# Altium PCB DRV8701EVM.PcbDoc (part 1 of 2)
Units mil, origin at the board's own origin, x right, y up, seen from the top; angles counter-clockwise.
Board outline 3500 x 2200 mil, 2 copper layers (Top Layer, Bottom Layer), stack 64.8 mil thick; 118 components, 65 nets, 313 pads, 397 vias.
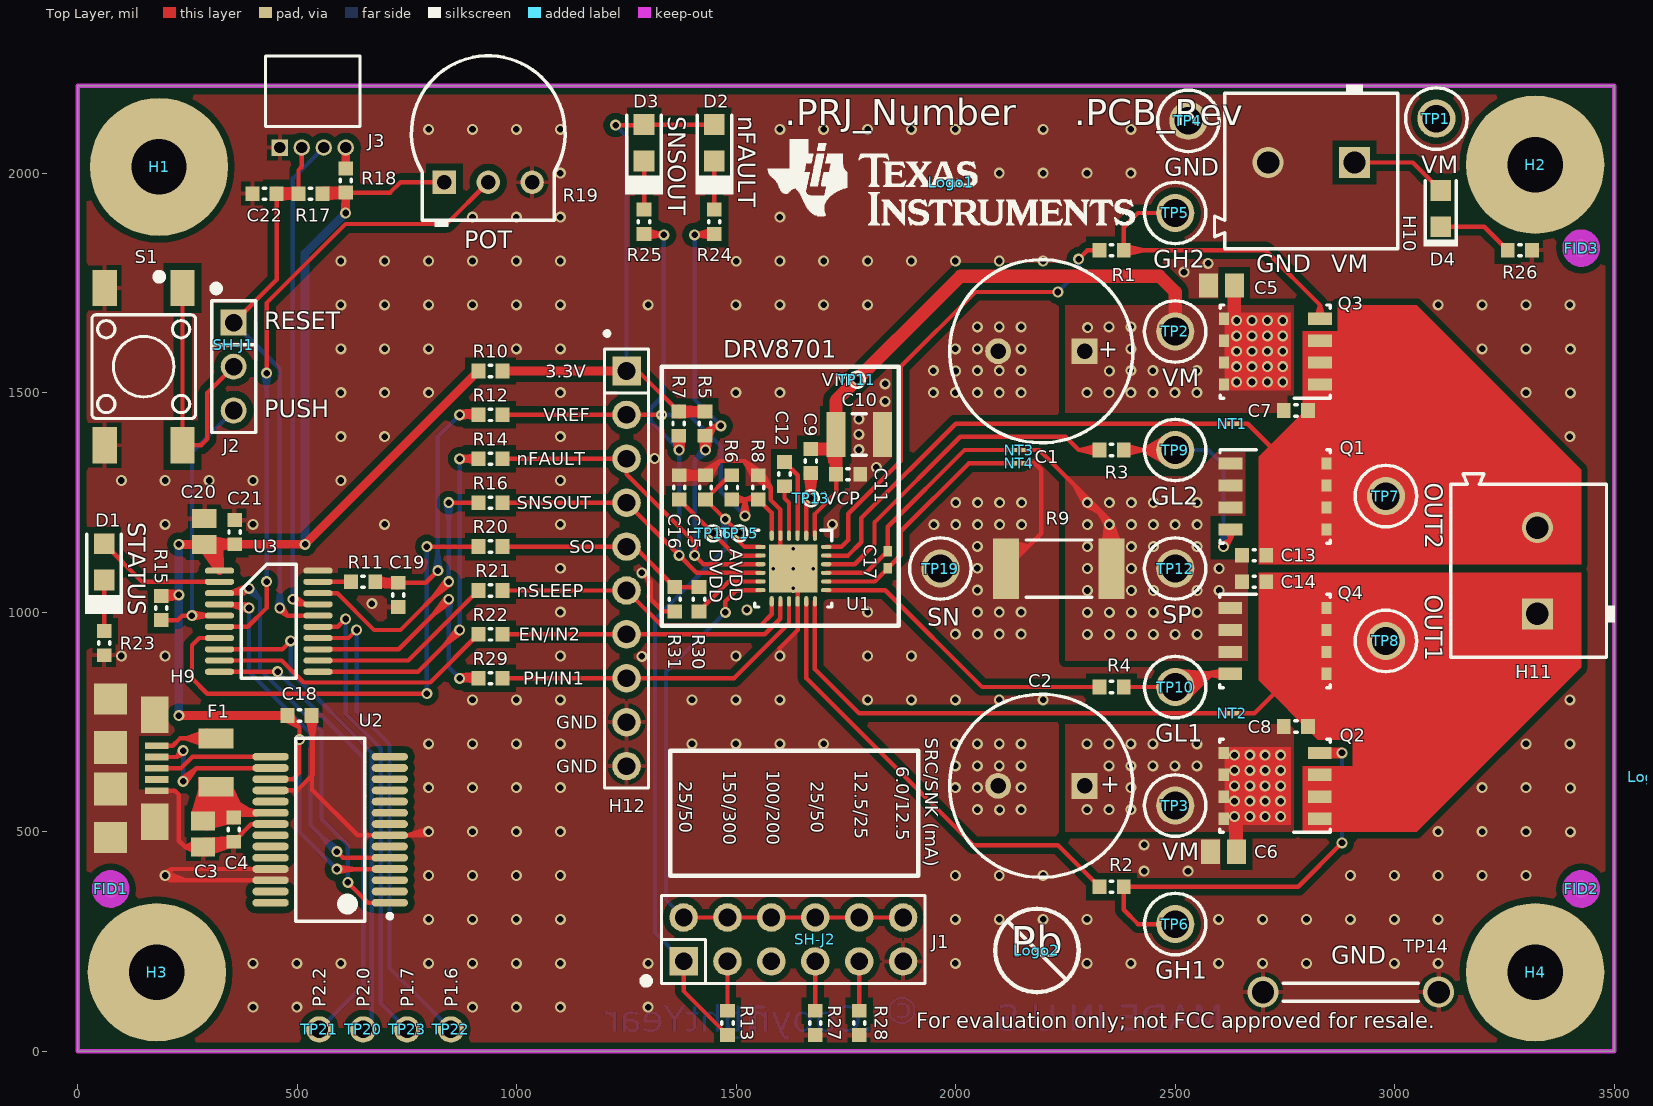
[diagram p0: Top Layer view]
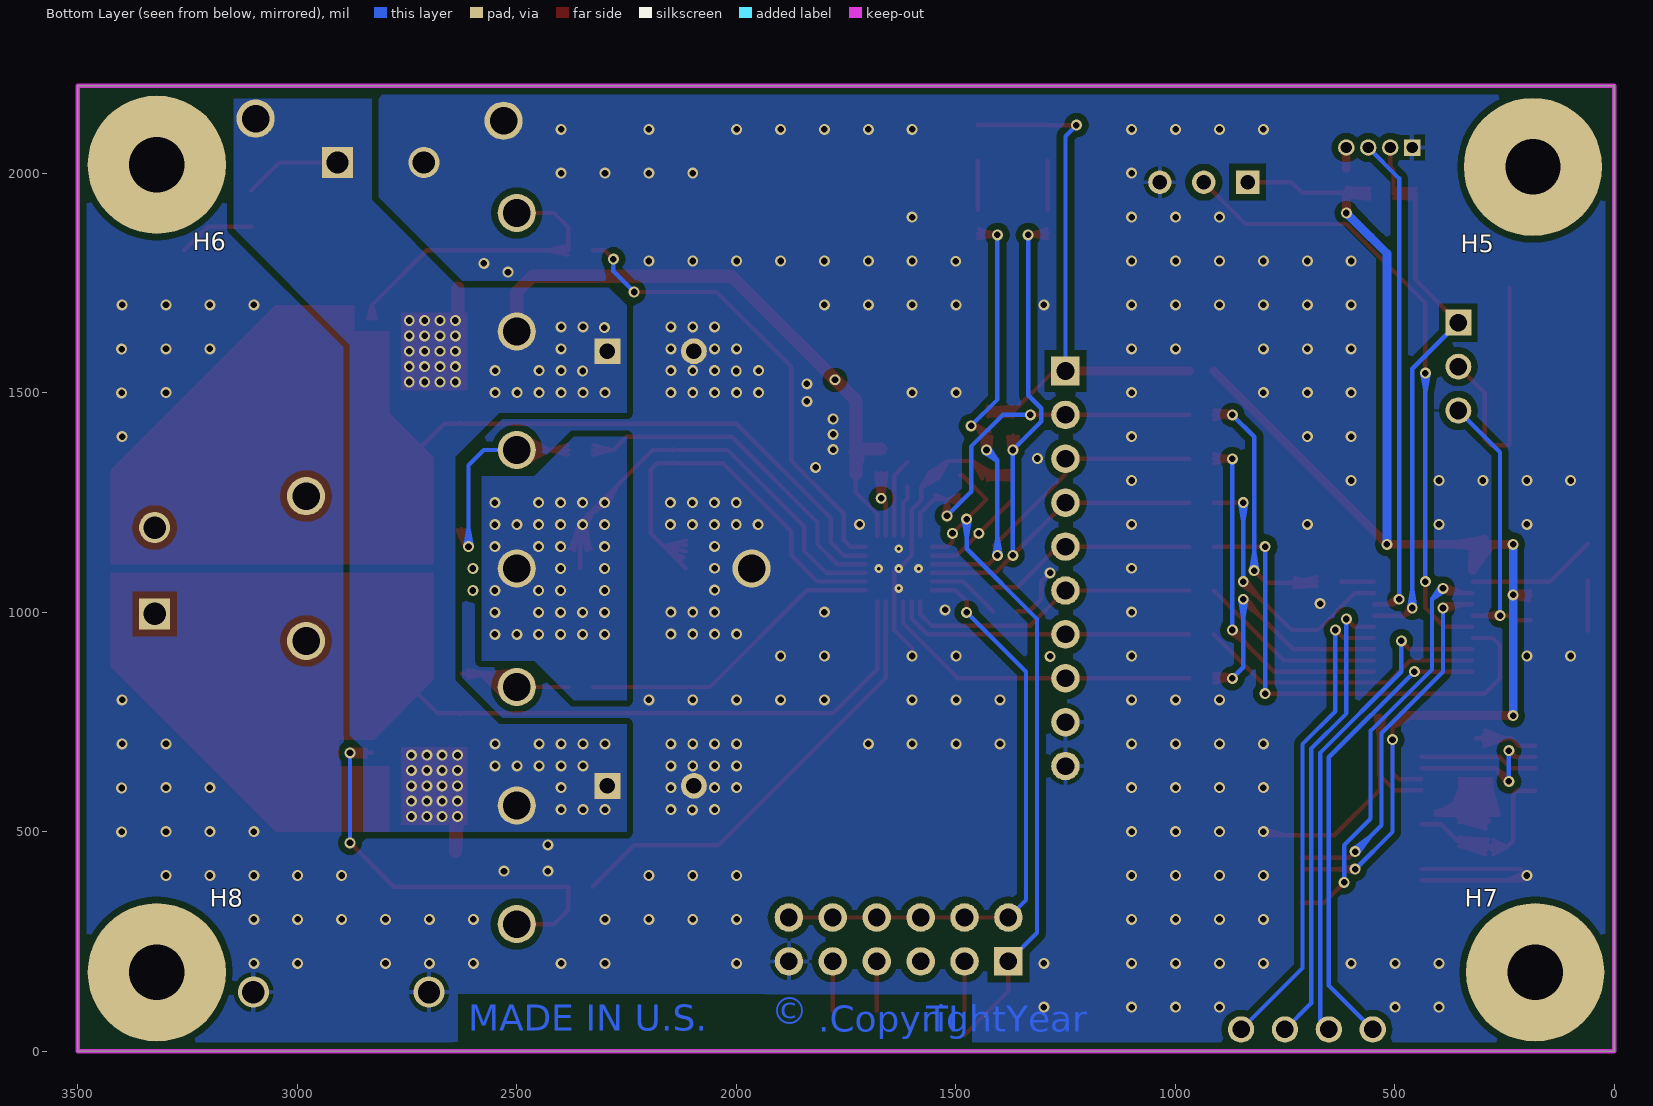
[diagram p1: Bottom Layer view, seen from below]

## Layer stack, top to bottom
Top Layer: signal copper 2.8
Dielectric: core 59.2, FR-4, Dk 4.8
Bottom Layer: signal copper 2.8

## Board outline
0,0 3500,0 3500,2200 0,2200

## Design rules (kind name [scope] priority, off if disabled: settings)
AcuteAngle [All] p1: minimum=4.50000000000000E+0001 checktracksonly=FALSE
AssemblyTestPointUsage [All] p1: valid=2
Clearance Clearance_BoardEdge_MountingHoles [OnCopper and InComponentClass('Mounting Holes') vs IsKeepOut] p1: gap=15
Clearance Clearance_BoardEdge_Poly [OnCopper and InPoly vs IsKeepOut] p2: gap=15
Clearance Clearance_BoardEdge [OnCopper and Not InComponentClass('Logo') and not InComponentClass('FiducialMark') and not InRegion(1000,500,4000,800) and Not IsKeepout vs IsKeepOut] p3: gap=15
Clearance Clearance_Poly [InPolygon] p4: gap=15
Clearance [All] p5: gap=7
ComponentClearance ComponentClearance_Shunt [InComponentClass('Header') vs InComponentClass('Shunt')] p1: gap=0 collisioncheckmode=3 verticalgap=0 showdistances=FALSE
ComponentClearance ComponentClearance_Logo [InComponentClass('Logo')] p2: gap=15 collisioncheckmode=3 verticalgap=10 showdistances=FALSE
ComponentClearance ComponentClearance_ScrewToNut [(HasFootprint('NY PMS 440 0025 PH')) vs (HasFootprint('Keystone_1902C'))] p3: gap=5 collisioncheckmode=3 verticalgap=10 showdistances=FALSE
ComponentClearance ComponentClearance_MountingHoles [InComponentClass('Mounting Holes')] p4: gap=15 collisioncheckmode=3 verticalgap=100000 showdistances=FALSE
ComponentClearance ComponentClearance_SmallPassives [HasFootprint('0201*') or HasFootprint('0402*') or HasFootprint('0508') or HasFootprint('0603*') or HasFootprint('0612') or HasFootprint('0805*') or HasFootprint('0815*') or HasFootprint('0830*') or HasFootprint('1206*') or HasFootprint('1210*') or HasFootprint('1808*') or HasFootprint('1812*') or HasFootprint('1825*') or HasFootprint('2010*') or HasFootprint('2220*') or HasFootprint('2225*') or HasFootprint('2512*') or HasFootprint('2728*') or HasFootprint('3518*') vs HasFootprint('0201*') or HasFootprint('0402*') or HasFootprint('0508') or HasFootprint('0603*') or HasFootprint('0612') or HasFootprint('0805*') or HasFootprint('0815*') or HasFootprint('0830*') or HasFootprint('1206*') or HasFootprint('1210*') or HasFootprint('1808*') or HasFootprint('1812*') or HasFootprint('1825*') or HasFootprint('2010*') or HasFootprint('2220*') or HasFootprint('2225*') or HasFootprint('2512*') or HasFootprint('2728*') or HasFootprint('3518*')] p5: gap=15 collisioncheckmode=3 verticalgap=10 showdistances=FALSE
ComponentClearance ComponentClearance_THtoSMT [IsThruComponent vs IsSMTComponent] p6: gap=15 collisioncheckmode=3 verticalgap=25 showdistances=FALSE
ComponentClearance ComponentClearance_THtoTH [IsThruComponent vs IsThruComponent] p7: gap=15 collisioncheckmode=3 verticalgap=15 showdistances=FALSE
ComponentClearance [All] p8: gap=15 collisioncheckmode=3 verticalgap=10 showdistances=FALSE
DiffPairsRouting [All] p1: maxlimit=100 minlimit=10 mostfreqgap=10 maxuncoupledlength=1000
FabricationTestPointUsage TestPointUsage [All] p1: valid=2 allowmultiple=FALSE
FabricationTestpoint Testpoint [All] p1: side=3 testpointundercomponent=TRUE minsize=40 maxsize=100 preferedsize=60 minholesize=0 maxholesize=40 preferedholesize=32 testpointgrid=1 allowsidetop=TRUE allowsidebottom=TRUE usegrid=TRUE gridtolerance=0.01
FanoutControl Fanout_LCC [IsLCC] p1: bgadir=Out bgaviamode=Centered fanoutstyle=Auto fanoutdirection=Alternating viagrid=1 // Fanout_LCC (Default Rule)
FanoutControl Fanout_BGA [IsBGA] p2: bgadir=Out bgaviamode=Centered fanoutstyle=Auto fanoutdirection=Alternating viagrid=1 // Fanout_BGA (Default Rule)
FanoutControl Fanout_Default [All] p4: bgadir=Out bgaviamode=Centered fanoutstyle=Auto fanoutdirection=Alternating viagrid=1 // Fanout_Default (Default Rule)
FanoutControl Fanout_Small [(CompPinCount < 5)] p5: bgadir=Out bgaviamode=Centered fanoutstyle=Auto fanoutdirection=OutThenIn viagrid=1 // Fanout_Small (Default Rule)
HoleSize [All] p1: absolutevalues=TRUE maxlimit=251 minlimit=8 maxpercent=80.000 minpercent=20.000
MinimumAnnularRing MinimumAnnularRing_ThermalPadVias [IsVia and InAnyComponent] p1: minimumring=3.9
MinimumAnnularRing [All] p2: minimumring=3.9
MinimumSolderMaskSliver MinimumSolderMaskSliver_Logo [InComponentClass('Logo') vs InComponentClass('Logo')] p1: minsoldermaskwidth=0.7
MinimumSolderMaskSliver [All] p2: minsoldermaskwidth=2
PlaneConnect [All] p1: planeconnectstyle=Relief reliefexpansion=10 reliefentries=4 reliefconductorwidth=10 reliefairgap=10
PolygonConnect PolygonConnect_1 [IsNamedPolygon('TOP_GND_PLN') or IsNamedPolygon('BOT_GND_PLN') vs Not (InComponent('U1') or InComponent('U2') or InComponent('U3') or InComponent('Q3') or InComponent('Q4') or InComponent('Q5') or InComponent('Q6') or InComponent('C1') or InComponent('C2') or InComponent('C5') or InComponent('C6') or InComponent('C10') or InComponent('C11') or InComponent('C15') or InComponent('C16') or InComponent('R8') or InComponent('R9') or InComponent('H9') or InComponent('H10') or InComponent('TP4') or IsStitchingVia or IsVia)] p1: connectstyle=Relief reliefconductorwidth=10 reliefentries=4 polygonreliefangle="90 Angle" airgapwidth=10
PolygonConnect [All] p2: connectstyle=Direct reliefconductorwidth=10 reliefentries=4 polygonreliefangle="90 Angle" airgapwidth=10
RoutingVias ThermalPadVias [IsVia and InAnyComponent] p1: holewidth=7.87 width=19.68 viastyle="Through Hole" minholewidth=7.87 minwidth=19.68 maxholewidth=12.99 maxwidth=23.62
RoutingVias [All] p2: holewidth=16 width=34 viastyle="Through Hole" minholewidth=7.87 minwidth=25 maxholewidth=40 maxwidth=65
SMDToCorner [All] p1: distance=30000
SilkToSilkClearance [All] p1: silktosilkclearance=5
SilkscreenOverComponentPads [IsPad] p1: minsilkscreentomaskgap=1.95
SolderMaskExpansion [All] p1: expansion=1.97
Width [All] p1: maxlimit=100 minlimit=6 preferedwidth=10 checkconnectedcopper=TRUE
14 further rules are at their usual default settings.

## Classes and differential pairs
component class Header: H12 J1 J2
component class AssemblyNote: ZZ1 ZZ2 ZZ3 ZZ4
component class DRV8701EVM_HARDWARE: FID1 FID2 FID3 H1 H2 H3 H4 H5 H6 H7 H8 Logo1 Logo2 Logo3 ZZ1 ZZ2 ZZ3 ZZ4
component class Logo: Logo1
component class DRV8701EVM_SCHEMATIC: C1 C2 C3 C4 C5 C6 C7 C8 C9 C10 C11 C12 C13 C14 C15 C16 C17 C18 C19 C20 C21 C22 D1 D2 D3 D4 F1 H9 H10 H11 H12 J1 J2 J3 NT1 NT2 NT3 NT4 Q1 Q2 Q3 Q4 R1 R2 R3 R4 R5 R6 R7 R8 R9 R10 R11 R12 R13 R14 R15 R16 R17 R18 R19 R20 R21 R22 R23 R24 R25 R26 R27 R28 R29 R30 R31 S1 SH-J1 SH-J2 TP1 TP2 TP3 TP4 TP5 TP6 TP7 TP8 TP9 TP10 TP11 TP12 TP13 TP14 TP15 TP16 TP19 TP20 TP21 TP22 TP23 U1 U2 U3
component class Shunt: SH-J1 SH-J2
component class FiducialMark: FID1 FID2 FID3
component class "Mounting Holes": H1 H2 H3 H4

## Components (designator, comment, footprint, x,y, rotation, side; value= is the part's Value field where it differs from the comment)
C1 "ECA-1HM471" M_1000x2000 2195,1595 r180 top
C2 "ECA-1HM471" M_1000x2000 2195,605 r180 top
C3 "C2012X7R1A475M" 0805L 285,495 r270 top
C4 "C0603C104K8RACTU" 0603L 355,505 r270 top
C5 "GRM21BR71H105KA12L" 0805L 2605,1745 r180 top
C6 "GRM21BR71H105KA12L" 0805L 2610,455 r180 top
C7 "DNP" 0603L 2775,1460 r0 top
C8 "DNP" 0603L 2775,740 r0 top
C9 "C1608X7R1C105K" 0603L 1670,1345 r90 top
C10 "GRM32ER71H106KA12L" 1210L 1780,1405 r0 top
C11 "C1608X7R1H104K" 0603L 1755,1315 r0 top
C12 "C1608X7R1H104K" 0603L 1610,1315 r270 top
C13 "DNP" 0603L 2680,1130 r180 top
C14 "DNP" 0603L 2680,1070 r180 top
C15 "GRM188R70J105KA01D" 0603L 1430,1285 r90 top
C16 "GRM188R70J105KA01D" 0603L 1370,1285 r270 top
C17 "GRM155R71C102KA01D" 0402L 1845,1120 r270 top
C18 "C0603C104K8RACTU" 0603L 505,765 r0 top
C19 "GRM188R70J105KA01D" 0603L 730,1040 r270 top
C20 "C2012X7R1A475M" 0805L 288.2,1184.8 r90 top
C21 "C0603C104K8RACTU" 0603L 357.2,1182.8 r90 top
C22 "GRM188R71C102KA01D" 0603L 425.21,1954 r180 top
D1 "LTST-C171GKT" LED_LTST-C171 60,1115 r270 top
D2 "LTST-C170KRKT" LED_LTST-C170 1450,2070 r270 top
D3 "LTST-C170KRKT" LED_LTST-C170 1290,2070 r270 top
D4 "LTST-C171GKT" LED_LTST-C171 3105,1920 r270 top
F1 "1206L050/15YR" 1206_FUSE 315,658 r270 top
FID1 "Fiducial" Fiducial10-20 75,370 r0 top
FID2 "Fiducial" Fiducial10-20 3425,370 r0 top
FID3 "Fiducial" Fiducial10-20 3425,1830 r0 top
H1 "NY PMS 440 0025 PH" "NY PMS 440 0025 PH" 185,2015 r0 top locked
H2 "NY PMS 440 0025 PH" "NY PMS 440 0025 PH" 3320,2020 r0 top locked
H3 "NY PMS 440 0025 PH" "NY PMS 440 0025 PH" 180,180 r0 top locked
H4 "NY PMS 440 0025 PH" "NY PMS 440 0025 PH" 3320,180 r0 top locked
H5 "1902C" Keystone_1902C 185.13,2015.01 r180 bottom
H6 "1902C" Keystone_1902C 3320.36,2020 r180 bottom
H7 "1902C" Keystone_1902C 180.36,180 r180 bottom
H8 "1902C" Keystone_1902C 3320.36,180 r180 bottom
H9 "ZX62-B-5PA(11)" CONN_USB_micro_ZX62-B-5PA 180,645 r270 top
H10 "691 101 710 002" Wurth_691101710002 2810,2025 r180 top
H11 "691 101 710 002" Wurth_691101710002 3325,1095 r90 top
H12 "TSW-110-07-G-S" TSW-110-07-G-S 1250,1100 r270 top
J1 "PEC06DAAN" CONN_PEC06DAAN 1630,255 r0 top
J2 "PEC03SAAN" CONN_PEC03SAAN 355,1560 r270 top
J3 "851-43-004-20-001000" CONN_851-43-004-20-001000 535.21,2059 r180 top
Logo1 "Texas Instruments" TI_Stacked_Overlay_Small 1990,1980 r0 top
Logo2 "Pb-Free Symbol" Pb-Free_Overlay_Medium 2185,230 r0 top
Logo3 "FCC disclaimer" FCC_disclaimer 3583,626 r90 top
NT1 "Net-Tie" Net-Tie_10mil 2630,1430 r0 top
NT2 "Net-Tie" Net-Tie_10mil 2630,770 r0 top
NT3 "Net-Tie" Net-Tie_10mil 2145,1370 r180 top
NT4 "Net-Tie" Net-Tie_10mil 2145,1340 r0 top
Q1 "CSD18532Q5B" TRANS_NexFET_Q5B 2720.3,1594.09 r180 top
Q2 "CSD18532Q5B" TRANS_NexFET_Q5B 2720,605 r180 top
Q3 "CSD18532Q5B" TRANS_NexFET_Q5B 2735.3,1264.09 r0 top
Q4 "CSD18532Q5B" TRANS_NexFET_Q5B 2735,935 r0 top
R1 "CRCW06030000Z0EA" 0603L 2355,1825 r180 top
R2 "CRCW06030000Z0EA" 0603L 2355,375 r0 top
R3 "CRCW06030000Z0EA" 0603L 2355,1370 r180 top
R4 "CRCW06030000Z0EA" 0603L 2355,830 r0 top
R5 "CRCW060310K0JNEA" 0603L 1428.7,1430 r270 top
R6 "DNP" 0603L 1490,1285 r90 top
R7 "CRCW060310K0JNEA" 0603L 1368.7,1430 r270 top
R8 "DNP" 0603L 1550,1285 r270 top
R9 "CRA2512-FZ-R010ELF" 2512M 2235,1100 r0 top
R10 "CRCW06030000Z0EA" 0603L 940,1550 r180 top
R11 "CRCW060310K0JNEA" 0603L 650,1070 r0 top
R12 "CRCW06030000Z0EA" 0603L 940,1450 r180 top
R13 "CRCW060368K0JNEA" 0603L 1480,65 r270 top
R14 "CRCW06030000Z0EA" 0603L 940,1350 r180 top
R15 "CRCW060347K0JNEA" 0603L 190,1010 r90 top
R16 "CRCW06030000Z0EA" 0603L 940,1250 r180 top
R17 "CRCW060347K0JNEA" 0603L 530.21,1954 r0 top
R18 "CRCW06030000Z0EA" 0603L 610.21,1984 r270 top
R19 "3352T-1-503LF" Bourns_3352T 935,1980 r0 top
R20 "CRCW06030000Z0EA" 0603L 940,1150 r180 top
R21 "CRCW06030000Z0EA" 0603L 940,1050 r180 top
R22 "CRCW06030000Z0EA" 0603L 940,950 r180 top
R23 "CRCW0603330RJNEA" 0603L 60,930 r90 top
R24 "CRCW0603330RJNEA" 0603L 1450,1890 r90 top
R25 "CRCW0603330RJNEA" 0603L 1290,1890 r90 top
R26 "CRCW06034K99FKEA" 0603L 3285,1825 r180 top
R27 "CRCW0603200KJNEA" 0603L 1680,65 r90 top
R28 "CRCW060333K0JNEA" 0603L 1780,65 r90 top
R29 "CRCW06030000Z0EA" 0603L 940,850 r180 top
R30 "CRCW06037K50JNEA" 0603L 1415,1030 r270 top
R31 "CRCW060310K0JNEA" 0603L 1360,1030 r270 top
S1 "4-1437565-1" SW_FSM4JSMA 150,1560 r0 top
SH-J1 "969102-0000-DA" SNT-100-BK-G 355,1610 r90 top
SH-J2 "969102-0000-DA" SNT-100-BK-G 1680,255 r90 top
TP1 "5005" Keystone5005 3095,2125 r0 top
TP2 "5005" Keystone5005 2500,1640 r0 top
TP3 "5005" Keystone5005 2500,560 r0 top
TP4 "5006" Keystone5006 2530,2120 r0 top
TP5 "5007" Keystone5007 2500,1910 r0 top
TP6 "5007" Keystone5007 2500,290 r0 top
TP7 "5007" Keystone5007 2980,1265 r0 top
TP8 "5007" Keystone5007 2980,935 r0 top
TP9 "5007" Keystone5007 2500,1370 r0 top
TP10 "5007" Keystone5007 2500,830 r0 top
TP11 "VM" TP_VIA_018RND008 1775,1530 r90 top
TP12 "5006" Keystone5006 2500,1100 r0 top
TP13 "VCP" TP_VIA_018RND008 1670,1260 r180 top
TP14 "D3082-05" Harwin_D3082-05 2900,135 r180 top
TP15 "AVDD" TP_VIA_018RND008 1507.44,1180 r0 top
TP16 "DVDD" TP_VIA_018RND008 1447.44,1180 r90 top
TP19 "5006" Keystone5006 1965,1100 r0 top
TP20 "TESTPOINT" TP_VIA_060RND040 650,50 r90 top
TP21 "TESTPOINT" TP_VIA_060RND040 550,50 r90 top
TP22 "TESTPOINT" TP_VIA_060RND040 850,50 r90 top
TP23 "TESTPOINT" TP_VIA_060RND040 750,50 r90 top
U1 "DRV8701ERGER" RGE0024F 1630,1100 r270 top
U2 "FT232RL" SSOP28_N 575,505 r180 top
U3 "MSP430G2553IPW20" PW0020A_N 435,980 r0 top
ZZ1 "This Assembly Note is for PCB labels only" AssemblyNoteLabel 185,2655 r0 top
ZZ2 "These assemblies are ESD sensitive, ESD precautions shall be observed." AssemblyNote 185,2569.11 r0 top
ZZ3 "These assemblies must be clean and free from flux and all contaminants. Use of no clean flux is not acceptable." AssemblyNote 185,2480.56 r0 top
ZZ4 "These assemblies must comply with workmanship standards IPC-A-610 Class 2, unless otherwise specified." AssemblyNote 185,2395 r0 top

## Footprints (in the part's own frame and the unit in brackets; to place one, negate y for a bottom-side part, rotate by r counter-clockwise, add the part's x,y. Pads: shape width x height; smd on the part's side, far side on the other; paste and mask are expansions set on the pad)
0402L [mm] "0402 from SM-752 data"
  rect 0.6x0.5 smd: 1(-0.5,0) 2(0.5,0)
  body extent -0.55,-0.3 0.55,0.3, height 0.6
0603L [mm] "0603 from SM-752 data"
  rect 0.8x0.85 smd: 1(-0.7,0) 2(0.7,0)
  silkscreen extent -0.07,-0.33 0.07,0.33, body extent -0.87,-0.47 0.87,0.47, height 0.85
0805L [mm] "0805 from SM-752 data"
  rect 1.1x1.4 smd: 1(-0.75,0) 2(0.75,0)
  body extent -1.1,-0.72 1.1,0.72, height 1.1
1206_FUSE [mil]
  rect 45x80 smd mask+2: 1(-55,0) 2(55,0)
1210L [mm] "1210 from SM-752 data"
  rect 1.1x2.6 smd: 1(-1.35,0) 2(1.35,0)
  silkscreen extent -0.4,-1.2 0.4,1.2, body extent -1.7,-1.35 1.7,1.35, height 1.35
2512M [mm] "Chip Resistor, Body 6.3x3.2mm, IPC Low Density"
  rect 1.5x3.5 smd: 1(-3.05,0) 2(3.05,0)
  silkscreen extent -1.9,-1.65 1.9,1.65, body extent -3.22,-1.67 3.22,1.67, height 0.71
AssemblyNote [mil] "Assembly Note"
AssemblyNoteLabel [mil] "Assembly Note for PCB Labels"
Bourns_3352T [mm] "TH, 3-Leads, Body 9.53x8.89mm, Pitch 2.54mm"
  rect 1.35x1.35 hole 0.85: 1(-2.54,0)
  round 1.35 hole 0.85: 2(0,0) 3(2.54,0)
  silkscreen extent -4.44,-2.6 4.44,7.31, body extent -4.44,-2.21 4.45,7.32, height 3.81
CONN_851-43-004-20-001000 [mm] "MILL-MAX"
  rect 0.95x0.95 hole 0.65: 1(1.905,0)
  round 0.95 hole 0.65: 2(0.635,0) 3(-0.635,0) 4(-1.905,0)
  silkscreen extent -2.73,-5.31 2.73,-1.22, body extent -2.73,-5.31 2.73,0.23, height 2.23
CONN_PEC03SAAN [mm] "SULLINS"
  rect 1.5x1.5 hole 1.016: 1(-2.54,0)
  round 1.5 hole 1.016: 2(0,0) 3(2.54,0)
  silkscreen extent -4.72,-1.27 3.81,1.27, body extent -3.84,-1.3 3.84,1.3, height 8.38
CONN_PEC06DAAN [mm] "SULLINS"
  rect 1.65x1.65 hole 1.016 mask+0: 1(-6.35,-1.27)
  round 1.65 hole 1.016 mask+0: 2(-6.35,1.27) 3(-3.81,-1.27) 4(-3.81,1.27) 5(-1.27,-1.27) 6(-1.27,1.27) 7(1.27,-1.27) 8(1.27,1.27) 9(3.81,-1.27) 10(3.81,1.27) 11(6.35,-1.27) 12(6.35,1.27)
  silkscreen extent -8.72,-2.6 7.62,2.54, body extent -7.62,-2.54 7.62,2.54, height 8.38
CONN_USB_micro_ZX62-B-5PA [mm] "Hirose"
  rect 0.4x1.35 smd: 1(-1.3,0) 2(-0.65,0) 3(0,0) 4(0.65,0) 5(1.3,0)
  rect 1.9x1.9 smd: 6(-1.2,-2.675) 7(1.2,-2.675)
  rect 1.8x1.9 smd: 8(-4,-2.675) 9(4,-2.675)
  rect 2.1x1.6 smd: 10(-3.1,-0.125) 11(3.1,-0.125)
  body extent -3.75,-5.32 3.75,0.18, height 2.55
FCC_disclaimer [mil]
Fiducial10-20 [mm]
  round 1 smd paste-0.5 mask+0.5: 1(0,0)
  Top Layer keep-out circle w1.178: c0,0 r0.5
Harwin_D3082-05 [mm] "Shorting Plug, 10.16mm spacing, TH"
  round 1.8 hole 1.3: 1(-5.08,0) 2(5.08,0)
  silkscreen extent -3.9,-0.53 3.9,0.53, body extent -5.6,-0.52 5.61,0.52, height 6.63
Keystone5005 [mil] "Keystone Compact loops"
  round 87 hole 63: 1(0,0)
  silkscreen extent -70,-70 70,70, body extent -63,-63 62,63, height 225
Keystone5006 [mil] "Keystone Compact loops"
  round 87 hole 63: 1(0,0)
  silkscreen extent -70,-70 70,70, body extent -63,-63 62,63, height 225
Keystone5007 [mil] "Keystone Compact loops"
  round 87 hole 63: 1(0,0)
  silkscreen extent -70,-70 70,70, body extent -63,-63 62,63, height 225
Keystone_1902C [mil] "Hex Standoff, 4-40 threaded, nylon"
  round 1 on Mech4: 0(0,0)
  body extent -145,-126 146,126, height 501
LED_LTST-C170 [mm] "LITE-ON"
  rect 1.2x1.2 smd: 1(-1.05,0) 2(1.05,0)
  silkscreen extent -1.6,-1.1 3,1.1, body extent -1.05,-0.67 1.05,0.67, height 1.1
LED_LTST-C171 [mm] "LITE-ON"
  rect 1.2x1.2 smd: 1(-1.05,0) 2(1.05,0)
  silkscreen extent -1.6,-1.1 3,1.1, body extent -1.05,-0.67 1.05,0.67, height 0.8
M_1000x2000 [mm] "Panasonic"
  rect 1.5x1.5 hole 0.9: 1(-2.5,0)
  round 1.5 hole 0.9: 2(2.5,0)
  silkscreen extent -5.3,-5.3 5.3,5.3, body extent -5.21,-5.24 5.24,5.24, height 22.01
Net-Tie_10mil [mil] "10mil net tie, no solder mask opening, no solder paste"
  rect 10x10 smd paste-5 mask-5: 1(-10,0) 2(10,0)
  Top Layer region: -6,5 6,5 6,-5 -6,-5
"NY PMS 440 0025 PH" [mm] "4-40 nylon screw and mounting hole"
  round 8 hole 3.2: 1(0,0)
  body extent -3.3,-3.3 3.3,3.3, height 2.69
Pb-Free_Overlay_Medium [mil]
  silkscreen extent -95,-95 95,95
PW0020A_N [mm] "TSOP, 20-Leads, Body 6.5x4.4mm, Pitch 0.65mm, IPC Medium Density"
  oval 1.7x0.35 smd: 1(-2.85,2.925) 2(-2.85,2.275) 3(-2.85,1.625) 4(-2.85,0.975) 5(-2.85,0.325) 6(-2.85,-0.325) 7(-2.85,-0.975) 8(-2.85,-1.625) 9(-2.85,-2.275) 10(-2.85,-2.925) 11(2.85,-2.925) 12(2.85,-2.275) 13(2.85,-1.625) 14(2.85,-0.975) 15(2.85,-0.325) 16(2.85,0.325) 17(2.85,0.975) 18(2.85,1.625) 19(2.85,2.275) 20(2.85,2.925)
  silkscreen extent -1.6,-3.3 1.6,3.3, body extent -3.21,-3.25 3.21,3.25, height 0.99
RGE0024F [mm] "QFN, 24-Leads, Body 4x4mm, Pitch 0.5mm, Thermal Pad 2.8x2.8mm, TI Recommended"
  oval 0.6x0.24 smd: 1(-1.9,1.25) 2(-1.9,0.75) 3(-1.9,0.25) 4(-1.9,-0.25) 5(-1.9,-0.75) 6(-1.9,-1.25) 13(1.9,-1.25) 14(1.9,-0.75) 15(1.9,-0.25) 16(1.9,0.25) 17(1.9,0.75) 18(1.9,1.25)
  oval 0.24x0.6 smd: 7(-1.25,-1.9) 8(-0.75,-1.9) 9(-0.25,-1.9) 10(0.25,-1.9) 11(0.75,-1.9) 12(1.25,-1.9) 19(1.25,1.9) 20(0.75,1.9) 21(0.25,1.9) 22(-0.25,1.9) 23(-0.75,1.9) 24(-1.25,1.9)
  rect 2.8x2.8 smd paste-1.4: 25(0,0)
  silkscreen extent -2.22,-2.22 2.22,2.22, body extent -2.07,-2.07 2.08,2.08, height 1.01
SNT-100-BK-G [mil] "Samtec STEP model"
  round 1 on Mech3: 0(0,0)
  body extent -100,-50 100,50, height 344
SSOP28_N [mm] "SOP, 28-Leads, Body 10.2x5.3mm, Pitch 0.65mm, IPC Medium Density"
  oval 2.1x0.45 smd mask+0.07: 1(-3.45,4.225) 2(-3.45,3.575) 3(-3.45,2.925) 4(-3.45,2.275) 5(-3.45,1.625) 6(-3.45,0.975) 7(-3.45,0.325) 8(-3.45,-0.325) 9(-3.45,-0.975) 10(-3.45,-1.625) 11(-3.45,-2.275) 12(-3.45,-2.925) 13(-3.45,-3.575) 14(-3.45,-4.225) 15(3.45,-4.225) 16(3.45,-3.575) 17(3.45,-2.925) 18(3.45,-2.275) 19(3.45,-1.625) 20(3.45,-0.975) 21(3.45,-0.325) 22(3.45,0.325) 23(3.45,0.975) 24(3.45,1.625) 25(3.45,2.275) 26(3.45,2.925) 27(3.45,3.575) 28(3.45,4.225)
  silkscreen extent -3.57,-5.3 2,5.3, body extent -2.7,-5.3 2.7,5.3, height 2
SW_FSM4JSMA [mm] "Alcoswitch"
  rect 1.4x2.1 smd: 1(2.25,4.55) 2(2.25,-4.55) 3(-2.25,4.55) 4(-2.25,-4.55)
  silkscreen extent -3,-3 3,5.4, body extent -3,-5 3,5, height 5.1
TI_Stacked_Overlay_Small [mil]
  silkscreen extent -418,-98 418,98
TP_VIA_018RND008 [mil] "TP_VIA_018RND008"
  round 25 hole 15: 1(0,0)
  silkscreen extent -18,-18 18,18
TP_VIA_060RND040 [mil] "TP_VIA_060RND040"
  round 60 hole 40: 1(0,0)
TRANS_NexFET_Q5B [mm] "TI recommended land pattern (nominal) November 2012"
  rect 1.372x0.71 smd paste-0.4: 1(-2.776,1.905) 2(-2.776,0.635) 3(-2.776,-0.635) 4(-2.776,-1.905)
  rect 0.59x0.71 smd paste-0.3: 5(2.776,-1.905) 6(2.776,-0.635) 7(2.776,0.635) 8(2.776,1.905)
  Top Layer region: -1.106,-2.26 2.744,-2.26 2.744,2.26 -1.106,2.26
  silkscreen extent -3.38,-2.7 3,2.7, body extent -3.23,-2.55 2.87,2.55, height 1.06
TSW-110-07-G-S [mm] "Samtec 100mil, 1x10, 230 mil above insulator"
  rect 1.65x1.65 hole 1.016 mask+0: 1(-11.43,0)
  round 1.65 hole 1.016 mask+0: 2(-8.89,0) 3(-6.35,0) 4(-3.81,0) 5(-1.27,0) 6(1.27,0) 7(3.81,0) 8(6.35,0) 9(8.89,0) 10(11.43,0)
  silkscreen extent -13.72,-1.27 12.7,1.27, body extent -12.7,-1.27 12.7,1.27, height 8.38
Wurth_691101710002 [mm] "Terminal Block, 5 mm, 2x1, TH"
  rect 1.8x1.8 hole 1.3: 1(-2.5,0)
  round 1.8 hole 1.3: 2(2.5,0)
  silkscreen extent -5,-4.5 5.6,5, body extent -5.6,-4 5.6,5, height 12.5

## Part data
C1 C2: "CAP, AL, 470 µF, 50 V, +/- 20%,  ohm, TH"
C3 C20: "CAP, CERM, 4.7uF, 10V, +/-20%, X7R, 0805"
C4 C18 C21: "CAP, CERM, 0.1uF, 10V, +/-10%, X7R, 0603"
C5 C6: "CAP, CERM, 1uF, 50V, +/-10%, X7R, 0805"
C7 C8 C13 C14: library part C1608X7R1H103K, "CAP, CERM, 0.01uF, 50V, +/-10%, X7R, 0603"
C9: "CAP, CERM, 1uF, 16V, +/-10%, X7R, 0603"
C10: "CAP, CERM, 10uF, 50V, +/-10%, X7R, 1210"
C11 C12: "CAP, CERM, 0.1uF, 50V, +/-10%, X7R, 0603"
C15 C16 C19: "CAP, CERM, 1uF, 6.3V, +/-10%, X7R, 0603"
C17: "CAP, CERM, 1000pF, 16V, +/-10%, X7R, 0402"
C22: "CAP, CERM, 1000pF, 16V, +/-10%, X7R, 0603"
D1 D4: "LED, Green, SMD"
D2 D3: "LED, Red, SMD"
F1: library part FUSE_1206L_SERIES, "Fuse, Poly Resetable PTC, 0.5A"
FID1 FID2 FID3: "Fiducial mark.  There is nothing to buy or mount."
H1 H2 H3 H4: "Machine Screw, Round, #4-40 x 1/4, Nylon, Philips panhead"
H5 H6 H7 H8: "Standoff, Hex, 0.5\"L #4-40 Nylon"
H9: "Connector, micro USB Type B, Receptacle, R/A, SMD"
H10 H11: "Terminal Block, 5 mm, 2x1, Tin, TH"
H12: "Header, 100mil, 10x1, Gold, TH"
J1: "Header, 100mil, 6x2, Tin, TH"
J2: "Header, 100mil, 3x1, Tin, TH"
J3: "SOCKET .050\" GRID SIP 4 POS R/A, TH"
Logo1: library part TI_Logo, "Texas Instrument Corporate Signature"
Logo2: library part Pb-Free
Logo3: library part FCC_disclaimer, "FCC_disclaimer"
NT1 NT2 NT3 NT4: "Single point connection between nets."
Q1 Q2 Q3 Q4: "MOSFET, N-CH, 60V, 172A, SON 5x6mm"
R1 R2 R3 R4 R10 R12 R14 R16 R18 R20 R21 R22 R29: "RES, 0 ohm, 5%, 0.1W, 0603"
R5 R7 R11: "RES, 10k ohm, 5%, 0.1W, 0603"
R6 R8: library part CRCW06030000Z0EA, "RES, 0 ohm, 5%, 0.1W, 0603"
R9: "RES, 0.01 ohm, 1%, 3W, 2512"
R13: "RES, 68k ohm, 5%, 0.1W, 0603"
R15 R17: "RES, 47k ohm, 5%, 0.1W, 0603"
R19: "Trimming Potentiometer, 50K, 0.5W, TH"
R23 R24 R25: "RES, 330 ohm, 5%, 0.1W, 0603"
R26: "RES, 4.99k ohm, 1%, 0.1W, 0603"
R27: "RES, 200k ohm, 5%, 0.1W, 0603"
R28: "RES, 33k ohm, 5%, 0.1W, 0603"
R30: "RES, 7.5 k, 5%, 0.1 W, 0603"
R31: "RES, 10 k, 5%, 0.1 W, 0603"
S1: "Switch, Tactile, SPST-NO, 0.05A, 12V, SMT"
SH-J1 SH-J2: "Shunt, 100mil, Gold plated, Black"
TP1 TP2 TP3: "Test Point, Compact, Red, TH"
TP4 TP12 TP19: "Test Point, Compact, Black, TH"
TP5 TP6 TP7 TP8 TP9 TP10: "Test Point, Compact, White, TH"
TP11 TP13 TP15 TP16: library part TESTPOINT, "TEST POINT.  No entry in BOM."
TP14: "1mm Uninsulated Shorting Plug, 10.16mm spacing, TH"
TP20 TP21 TP22 TP23: "TEST POINT.  No entry in BOM."
U1: "H-Bridge Gate Driver, RGE0024F"
U2: "USB to Serial UART, SSOP28"
U3: "16 MHz Mixed Signal Microcontroller with 16 KB Flash, 512 B SRAM and 24 GPIOs, -40 to 85 degC, 20-pin SOP (PW), Green (RoHS & no Sb/Br)"
ZZ1: library part AssemblyNoteLabel
ZZ2 ZZ3 ZZ4: library part AssemblyNote

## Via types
v1: diameter 25, hole 15, Top Layer to Bottom Layer, tented both sides, 392 vias
v2: diameter 20, hole 8, Top Layer to Bottom Layer, 5 vias

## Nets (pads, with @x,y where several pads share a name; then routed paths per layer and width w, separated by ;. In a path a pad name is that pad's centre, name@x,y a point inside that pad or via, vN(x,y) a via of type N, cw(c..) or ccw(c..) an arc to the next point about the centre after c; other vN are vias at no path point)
3.3V: D2.1 D3.1 H12.1 R5.1 R7.1 R10.1 | length 1987.1
  Top Layer w10: v1(1225,2110) 1288.66,2110 D3.1@1290,2111.34 D2.1@1450,2111.34 ; H12.1@1250,1550 1276.26,1550 R7.1@1368.7,1457.56 R5.1@1428.7,1457.56 ; R7.1@1369.05,1446.83 R5.1@1415.66,1449.48 ; R7.1@1369.05,1468.29 R5.1@1415.66,1465.64 ; R7.1@1372.75,1447.26 R5.1@1415.66,1465.64 ; R7.1@1372.75,1467.86 R5.1@1415.66,1449.48 ; R5.1@1426.45,1446.89 R7.1@1381.97,1457.56 ; R5.1@1426.45,1468.23 R7.1@1381.97,1457.56 ; R5.1@1427.72,1457.56 R7.1@1381.97,1457.56 ; R7.1@1369.69,1457.56 R5.1@1415.43,1457.56 ; R7.1@1369.69,1457.56 R5.1@1415.66,1449.48 ; R7.1@1369.69,1457.56 R5.1@1415.66,1465.64 ; R7.1@1369.69,1457.56 R5.1@1415.43,1457.56 ; R5.1@1415.43,1457.56 1370.95,1468.23 R5.1@1415.43,1457.56 ; R5.1@1415.43,1457.56 1370.95,1446.89 R5.1@1415.43,1457.56
  Top Layer w20: R10.1@967.56,1550 H12.1@1250,1550
  Bottom Layer w10: v1(1225,2110) 1250,2085 H12.1@1250,1550
3.3V_MCU: C18.1 C20.1 C21.1 R10.2 R15.2 R17.2 R18.2 R19.1 U2.4 U2.17 U3.1 | length 7062.6
  Top Layer w10: R15.2@190,1037.56 R15.2@192.44,1040 ; v1@226.84,1046.8 R15.2@193.12,1027.03 ; v1@227.72,1032.86 R15.2@191.79,1048.28 ; v1@228.82,1047.41 R15.2@190.98,1037.56 ; v1@229.25,1032.54 R15.2@192.44,1040 ; v1@229.25,1047.46 R15.2@192.44,1040 ; v1@229.75,1032.5 R15.2@190.98,1037.56 ; v1@230.88,1047.45 R15.2@191.79,1048.28 ; v1@231.8,1032.72 R15.2@193.12,1027.03 ; C20.1@287.93,1155 C20.1@288.2,1155.27 ; U2.17@439.17,620.16 490.16,620.16 ; C18.1@471.14,755.31 505,737.44 ; U2.17@471.65,620.16 490.16,620.16 ; C18.1@477.44,764.02 505,737.44 ; C18.1@477.44,765 505,737.44 ; C18.1@485.91,770.63 505,737.44 ; R17.2@556.48,1965.66 R18.2@602.54,1965.82 ; R17.2@557.57,1942.27 R18.2@603.56,1946.83 ; R17.2@557.77,1953.02 R18.2@603.56,1946.83 ; R17.2@557.77,1954 560.21,1956.45 R18.2@610.21,1956.45 711.45,1956.45 735,1980 R19.1@835,1980 ; R17.2@560.44,1963.43 R18.2@603.56,1946.83 ; R17.2@561.5,1944.91 R18.2@602.54,1965.82 ; v1(590,415) 710.39,415 U2.4@710.83,415.43 ; v1@590.66,407.53 632.5,415 v1@590.66,422.47 ; R18.2@607.96,1945.77 R17.2@563.48,1956.45 ; R18.2@607.96,1967.12 R17.2@563.48,1956.45 ; R18.2@609.22,1956.45 R17.2@563.48,1956.45 ; v1(610,1910) v1@610.21,1910.21 ; 639.49,415 U2.4@678.35,415.43 ; R15.2@190.98,1037.56 v1(230,1040) ; R15.2@190.98,1037.56 v1(230,1040) ; R15.2@191.79,1048.28 v1(230,1040) ; R15.2@191.79,1048.28 v1(230,1040) ; R15.2@192.44,1040 v1(230,1040) ; R15.2@192.44,1040 v1(230,1040) ; R15.2@193.12,1027.03 v1(230,1040) ; R15.2@193.12,1027.03 v1(230,1040) ; 490.16,620.16 505,635 v1(505,710) 505,737.44 ; R17.2@557.77,1954.99 R18.2@603.62,1956.45 ; R17.2@557.77,1954.99 R18.2@602.54,1965.82 ; R17.2@557.77,1954.99 R18.2@603.66,1956.45 ; R18.2@603.62,1956.45 558.69,1965.7 R18.2@603.66,1956.45 ; R18.2@603.62,1956.45 559.36,1944.36 R18.2@603.66,1956.45
  Top Layer w20: v1(230,765) C18.1@477.44,765 401.69,765 ; v1(230,1155) C21.1@357.17,1155 ; C20.1@280.47,1155 C21.1@356.22,1155.24 ; C20.1@284.07,1149.35 U3.1@322.8,1095.16 ; C20.1@284.29,1148.99 U3.1@322.17,1100.6 ; C20.1@295.14,1143.66 C21.1@357.17,1155 ; C20.1@295.19,1166.88 C21.1@357.17,1155.27 ; C20.1@295.24,1166.87 C21.1@357.17,1155 ; C20.1@304.94,1159.59 U3.1@322.17,1100.6 ; C20.1@305.03,1159.35 U3.1@322.8,1095.16 ; C21.1@357.2,1155.24 v1(517.68,1155.24) ; C21.1@358.19,1155.24 433.94,1155.24 ; 445.18,1155.24 v1(517.68,1155.24) ; R10.2@912.44,1550 v1(517.68,1155.24) ; C20.1@294.11,1155.27 322.17,1155.27 ; C20.1@294.11,1155.27 U3.1@322.17,1100.6 ; C20.1@294.11,1155.27 U3.1@322.8,1095.16 ; C20.1@294.11,1155.27 322.17,1155.27 ; C20.1@294.11,1155.27 C21.1@357.17,1155 ; C20.1@294.11,1155.27 C21.1@357.17,1155.27 ; C20.1@294.11,1155.27 C21.1@356.22,1155.24 ; C20.1@294.11,1155.27 C21.1@356.22,1155.24 ; C20.1@295.19,1143.67 C21.1@357.17,1155.27 ; C20.1@295.2,1143.67 C21.1@356.22,1155.24 ; C20.1@295.2,1143.67 C21.1@356.22,1155.24 ; U3.1@322.17,1100.6 322.17,1155.27 ; 322.17,1155.27 U3.1@322.8,1095.16 ; 322.17,1155.27 296.53,1166.67 322.17,1155.27 ; 322.17,1155.27 296.53,1143.87 322.17,1155.27 ; C21.1@356.22,1155.24 C20.1@288.2,1155.27 C21.1@357.17,1155.27 ; C21.1@356.22,1155.24 295.21,1166.87 C21.1@356.22,1155.24 ; R18.2@610.21,1956.45 610.21,1910.21 R18.2@610.21,1956.45 ; R18.2@610.21,1956.45 v1(610,1910) R18.2@610.21,1956.45
  Bottom Layer w10: v1@225,1155 v1@225.21,1155.21 ; v1(505,710) 505,500 v1(590,415)
  Bottom Layer w20: v1(230,765) v1(230,1155) 230,1082.5 ; 230,967.5 v1(230,1040) ; v1(517.68,1155.24) 517.68,1817.68 v1(610,1910) 555.07,1855.07
5V_USB: C3.1 C4.1 F1.2 U2.20 | length 1294.7
  Top Layer w10: C3.1@285,524.53 293.03,532.56 C4.1@355,532.56 ; C3.1@288.43,541 C4.1@341.63,540.56 ; C3.1@289.3,530.98 C4.1@341.63,540.56 ; C3.1@290.31,531.15 C4.1@343.16,532.56 ; C3.1@290.33,531.16 C4.1@344.72,532.56 ; C3.1@291.14,517.88 C4.1@347.23,523.21 ; C3.1@291.45,531.16 C4.1@347.23,523.21 ; C3.1@292.29,518.02 C4.1@344.72,532.56 ; C3.1@292.33,518.03 C4.1@343.16,532.56 ; C3.1@292.98,508 C4.1@347.23,523.21 ; C3.1@293.3,518.32 C4.1@341.63,540.56 ; C3.1@293.75,540.94 C4.1@347.23,523.21 ; C3.1@295.86,508.63 C4.1@344.72,532.56 ; C3.1@296,508.67 C4.1@343.16,532.56 ; C3.1@298.35,509.63 C4.1@341.63,540.56 ; C4.1@352.75,521.89 C3.1@308.27,532.56 ; C4.1@352.75,543.23 C3.1@308.27,532.56 ; C4.1@354.02,532.56 C3.1@308.27,532.56 ; C3.1@290.91,524.53 C4.1@343.16,532.56 ; C3.1@290.91,524.53 C4.1@347.23,523.21 ; C3.1@290.91,524.53 C4.1@344.72,532.56 ; C3.1@290.91,524.53 C4.1@341.63,540.56 ; C4.1@343.16,532.56 291,541.18 C4.1@344.72,532.56
AVDD: C15.1 J1.1 R6.2 R13.2 TP15.1 U1.7 | length 1701.3
  Top Layer w10: J1.1@1380,205 1380,137.44 R13.2@1480,37.44 ; R6.2@1490,1312.56 1485.12,1312.56 C15.1@1430,1257.44 TP15.1@1507.44,1180 1507.44,1160.71 1518.94,1149.21 U1.7@1555.2,1149.21
  Bottom Layer w10: J1.1@1380,205 1315,270 1315,985 1475,1145 v1(1475,1212.44) 1475,1169.94 ; v1@1467.53,1211.78 1475,1169.94 ; v1@1482.47,1211.78 1475,1169.94
DM: H9.2 U2.16 | length 559.3
  Top Layer w10: H9.2@180,670.59 225.59,670.59 ; H9.2@198.7,670.59 225.59,670.59 ; v1@233.81,689.24 225.59,670.59 ; v1@235.19,620.75 270,645 ; v1(240,615) 270,645 ; v1@244.24,678.81 225.59,670.59 ; v1@245.75,610.19 270,645 ; 367.83,645 U2.16@406.69,645.75 ; U2.16@439.17,645 270,645 ; 225.59,670.59 v1(240,685) 225.59,670.59
  Bottom Layer w10: v1(240,615) v1(240,685)
DP: H9.3 U2.15 | length 345.2
  Top Layer w10: H9.3@180,645 235,645 ; H9.3@198.7,645 235,645 ; 367.83,671.34 U2.15@406.69,671.34 ; U2.15@439.17,671.34 261.34,671.34 235,645
DVDD: C16.2 TP16.1 U1.8 | length 238.2
  Top Layer w10: C16.2@1370,1257.44 1497.91,1129.53 U1.8@1555.2,1129.53
EN/IN2: H12.7 R22.1 U1.14 | length 687.3
  Top Layer w10: R22.1@967.56,950 H12.7@1250,950 1565,950 1600.47,985.47 U1.14@1600.47,1025.2
EN/IN2_MCU: R22.2 U3.9 | length 692.8
  Top Layer w10: U3.9@322.8,890.43 464.57,890.43 514.76,840.24 802.68,840.24 R22.2@912.44,950 ; U3.9@349.37,890.43 386.26,890.43
GH1: R2.1 U1.17 | length 1039.6
  Top Layer w10: U1.17@1659.53,1025.2 1659.53,850.47 2040,470 2232.44,470 R2.1@2327.44,375
GH2: R1.2 U1.24 | length 1079.7
  Top Layer w10: U1.24@1704.8,1149.21 1739.21,1149.21 1755,1165 1755,1225 1875,1345 1875,1560 2045,1730 v1(2232.44,1730) ; v1(2280,1805) 2300,1825 R1.2@2327.44,1825
  Bottom Layer w10: v1(2232.44,1730) 2280,1777.56 v1(2280,1805)
GL1: R4.1 U1.19 | length 714.1
  Top Layer w10: U1.19@1704.8,1050.79 1839.21,1050.79 2060,830 R4.1@2327.44,830
GL2: R3.2 U1.22 | length 921.7
  Top Layer w10: U1.22@1704.8,1110 1770,1110 1815,1155 1815,1205 2010,1400 2250,1400 2280,1370 R3.2@2327.44,1370 2281.69,1370 ; R3.2@2326.18,1359.33 2281.69,1370 ; R3.2@2326.18,1380.67 2281.69,1370
GND: C1.2 C2.2 C3.2 C4.2 C5.2 C6.2 C10.2 C11.2 C15.2 C16.1 C18.2 C19.2 C20.2 C21.2 C22.2 H9.5 H9.6 H9.7 H9.8 H9.9 H9.10 H9.11 H10.2 H12.9 H12.10 J1.11 J3.1 NT4.2 R8.1 R9.1 R19.3 R23.1 R26.1 R27.1 R28.1 R31.2 S1.3 S1.4 TP4.1 TP14.1 TP14.2 TP19.1 U1.5 U1.16 U1.25 U2.7 U2.18 U2.21 U2.25 U2.26 U3.20 | length 6338.5
  Top Layer w10: H9.5@180,593.82 221.18,593.82 ; v1@194.85,406.8 213.92,415.43 ; v1@197.99,393.21 245.27,389.84 ; H9.5@198.7,593.82 221.18,593.82 ; v1@201.4,407.78 245.27,389.84 ; v1@205.29,396.36 213.92,415.43 ; C3.2@275.08,449.31 244.53,465.47 ; C3.2@275.08,481.64 244.53,465.47 ; C3.2@278.45,458.85 244.53,465.47 ; C3.2@278.45,472.1 244.53,465.47 ; C3.2@279.09,465.47 244.53,465.47 ; C3.2@287.24,481.72 C4.2@342.4,485.63 ; C3.2@288.86,471.8 C4.2@342.4,485.63 ; C3.2@289.85,472.04 C4.2@344.16,477.44 ; C3.2@289.89,472.05 C4.2@346.64,477.44 ; C3.2@291.04,472.12 C4.2@349.32,467.59 ; C3.2@291.52,458.85 C4.2@349.32,467.59 ; C3.2@292.68,459.06 C4.2@346.64,477.44 ; C3.2@292.68,482.03 C4.2@349.32,467.59 ; C3.2@292.76,459.08 C4.2@344.16,477.44 ; C3.2@293.7,459.43 C4.2@342.4,485.63 ; C3.2@293.87,449.09 C4.2@349.32,467.59 ; C3.2@296.74,449.88 C4.2@346.64,477.44 ; C3.2@296.99,449.97 C4.2@344.16,477.44 ; C3.2@299.24,451.06 C4.2@342.4,485.63 ; C4.2@352.75,466.77 C3.2@308.27,477.44 ; C4.2@352.75,488.11 C3.2@308.27,477.44 ; C4.2@354.02,477.44 C3.2@308.27,477.44 ; 367.83,389.84 U2.26@406.69,389.84 ; 367.83,415.43 U2.25@406.69,415.43 ; U2.26@439.17,389.84 209.91,389.84 v1(199.12,400.63) ; U2.25@439.17,415.43 213.92,415.43 ; U2.21@439.17,517.8 395.35,517.8 ; U2.18@439.17,594.57 499.57,594.57 ; U2.18@471.65,594.57 499.57,594.57 ; C18.2@521.89,762.75 532.56,718.27 ; C18.2@521.97,762.19 535,718.13 ; C18.2@532.56,765 532.56,627.56 ; C18.2@535,765 535,630 532.56,627.56 ; C18.2@543.23,762.75 532.56,718.27 ; C18.2@543.29,763.33 535,718.13 ; 639.49,492.2 U2.7@678.35,492.2 ; U2.7@743.31,492.2 782.17,492.2 ; v1@797.21,507.88 752.39,492.2 ; v1@799.86,493.17 752.39,492.2 ; v1(1285,1090) 1305,1070 1305,1030 1332.56,1002.44 R31.2@1360,1002.44 ; C16.1@1370,1312.56 C15.2@1430,1312.56 1462.44,1345 ; C16.1@1370.35,1301.83 C15.2@1416.96,1304.48 ; C16.1@1370.35,1323.29 C15.2@1416.96,1320.64 ; C16.1@1374.05,1302.26 C15.2@1416.96,1320.64 ; C16.1@1374.05,1322.86 C15.2@1416.96,1304.48 ; C15.2@1424.21,1320.91 1462.44,1345 ; C15.2@1427.75,1301.89 C16.1@1383.27,1312.56 ; C15.2@1427.75,1323.23 C16.1@1383.27,1312.56 ; C15.2@1429.02,1312.56 C16.1@1383.27,1312.56 ; C15.2@1430.98,1312.56 1462.44,1345 ; C15.2@1439.54,1306.05 1462.44,1345 ; R8.1@1540.46,1306.05 1517.56,1345 ; R8.1@1544.33,1304.12 1578.73,1283.83 ; R8.1@1549.02,1312.56 1517.56,1345 ; R8.1@1550.98,1312.56 1578.73,1283.83 ; R8.1@1555.79,1320.91 1517.56,1345 ; R8.1@1559.65,1318.92 1578.73,1283.83 ; v1(1599.12,900.63) 1599.12,919.12 1639.84,959.84 U1.16@1639.84,1025.2 ; U1.16@1639.84,1021.26 1639.84,1090.16 v2(1630,1100) 1600.47,1129.53 1600.47,1234.53 1578.73,1256.27 1578.73,1283.83 ; R9.1@2113.76,1153.85 2165.66,1150.74 ; R9.1@2114.92,1100 2195,1180.08 2195,1325 2180,1340 NT4.2@2155,1340 ; R9.1@2114.92,1139.37 2165.66,1150.74 ; R9.1@2115.35,1163.89 2165.66,1150.74 ; R9.1@2120.05,1125.78 2165.66,1150.74 ; R9.1@2125.78,1117.38 2165.66,1150.74 ; v1(199.12,400.63) 213.92,415.43 ; v1(199.12,400.63) 245.27,389.84 ; 221.18,593.82 230,585 230,480 244.53,465.47 ; 244.53,465.47 C3.2@285,465.47 296.97,477.44 C4.2@355,477.44 395.35,517.8 ; C3.2@290.91,465.47 C4.2@344.16,477.44 ; C3.2@290.91,465.47 C4.2@342.4,485.63 ; C3.2@290.91,465.47 C4.2@346.64,477.44 ; C3.2@290.91,465.47 C4.2@349.32,467.59 ; C4.2@344.16,477.44 289.78,482.09 C4.2@346.64,477.44 ; 395.35,517.8 406.69,517.8 395.35,517.8 ; 499.57,594.57 532.56,627.56 ; 532.56,627.56 532.56,597.44 637.8,492.2 U2.7@710.83,492.2 790.69,492.2 v1(799.12,500.63) 752.39,492.2 ; 532.56,718.27 532.56,764.02 535,718.13 ; C16.1@1370.98,1312.56 C15.2@1416.73,1312.56 ; C16.1@1370.98,1312.56 C15.2@1416.96,1304.48 ; C16.1@1370.98,1312.56 C15.2@1416.96,1320.64 ; C16.1@1370.98,1312.56 C15.2@1416.73,1312.56 ; C15.2@1416.73,1312.56 1372.25,1323.23 C15.2@1416.73,1312.56 ; C15.2@1416.73,1312.56 1372.25,1301.89 C15.2@1416.73,1312.56 ; 1462.44,1345 1517.56,1345 ; 1517.56,1345 R8.1@1550,1312.56 1578.73,1283.83
  other v1: 399.12,100.63 499.12,100.63 899.12,100.63 999.12,100.63 1099.12,100.63 1299.12,100.63 399.12,200.63 499.12,200.63 599.12,200.63 799.12,200.63 899.12,200.63 999.12,200.63 1099.12,200.63 1299.12,200.63 1999.12,200.63 2299.12,200.63 2399.12,200.63 2599.12,200.63 2699.12,200.63 2799.12,200.63 2999.12,200.63 3099.12,200.63 799.12,300.63 899.12,300.63 999.12,300.63 1099.12,300.63 1999.12,300.63 2099.12,300.63 2199.12,300.63 2299.12,300.63 2599.12,300.63 2699.12,300.63 2799.12,300.63 2899.12,300.63 2999.12,300.63 3099.12,300.63 799.12,400.63 899.12,400.63 999.12,400.63 1099.12,400.63 1999.12,400.63 2099.12,400.63 2199.12,400.63 2899.12,400.63 2999.12,400.63 3099.12,400.63 3199.12,400.63 3299.12,400.63 2429.12,410.63 2529.12,410.63 2429.12,470.63 3400,500 899.12,500.63 999.12,500.63 1099.12,500.63 3099.12,500.63 3199.12,500.63 3299.12,500.63 2100,550 2049.12,550.63 2149.12,550.63 3400,600 799.12,600.63 899.12,600.63 999.12,600.63 1099.12,600.63 1999.12,600.63 2049.12,600.63 2149.12,600.63 3199.12,600.63 3299.12,600.63 1999.12,650.63 2049.12,650.63 2099.12,650.63 2149.12,650.63 799.12,700.63 899.12,700.63 999.12,700.63 1099.12,700.63 1399.12,700.63 1499.12,700.63 1599.12,700.63 1699.12,700.63 1999.12,700.63 2049.12,700.63 2099.12,700.63 2149.12,700.63 3299.12,700.63 3399.12,700.63 899.12,800.63 999.12,800.63 1099.12,800.63 1399.12,800.63 1499.12,800.63 1599.12,800.63 1799.12,800.63 1899.12,800.63 1999.12,800.63 2099.12,800.63 2199.12,800.63 3399.12,800.63 1285,900 99.12,900.63 199.12,900.63 1099.12,900.63 1499.12,900.63 1799.12,900.63 1899.12,900.63 1999.12,950.63 2049.12,950.63 2099.12,950.63 2149.12,950.63 1099.12,1000.63 1799.12,1000.63 2049.12,1000.63 2099.12,1000.63 2149.12,1000.63 1524.12,1005.63 670,1020 2049.12,1050.63 1099.12,1100.63 2049.12,1100.63 2049.12,1150.63 1950,1200 2000,1200 2050,1200 2100,1200 2150,1200 199.12,1200.63 399.12,1200.63 699.12,1200.63 1099.12,1200.63 1719.12,1200.63 2000,1250 2050,1250 2100,1250 2150,1250 99.12,1300.63 199.12,1300.63 299.12,1300.63 399.12,1300.63 599.12,1300.63 1099.12,1300.63 1819.12,1330.63 1314.12,1350.63 1779.12,1370.63 599.12,1400.63 699.12,1400.63 1099.12,1400.63 3399.12,1400.63 1779.12,1405.63 1779.12,1440.63 1839.12,1480.63 3400,1500 599.12,1500.63 699.12,1500.63 799.12,1500.63 1099.12,1500.63 1499.12,1500.63 1599.12,1500.63 1949.12,1500.63 1999.12,1500.63 2049.12,1500.63 2099.12,1500.63 2149.12,1500.63 3299.12,1500.63 1839.12,1520.63 2000,1550 1949.12,1550.63 2049.12,1550.63 2099.12,1550.63 2149.12,1550.63 3400,1600 599.12,1600.63 699.12,1600.63 799.12,1600.63 999.12,1600.63 1099.12,1600.63 1999.12,1600.63 2049.12,1600.63 2149.12,1600.63 3199.12,1600.63 3299.12,1600.63 2049.12,1650.63 2099.12,1650.63 2149.12,1650.63 599.12,1700.63 699.12,1700.63 799.12,1700.63 899.12,1700.63 999.12,1700.63 1099.12,1700.63 1299.12,1700.63 1499.12,1700.63 1599.12,1700.63 1699.12,1700.63 1799.12,1700.63 3099.12,1700.63 3199.12,1700.63 3299.12,1700.63 3399.12,1700.63 2520,1775 2575,1795 1500,1800 599.12,1800.63 699.12,1800.63 799.12,1800.63 899.12,1800.63 999.12,1800.63 1099.12,1800.63 1599.12,1800.63 1699.12,1800.63 1799.12,1800.63 1899.12,1800.63 1999.12,1800.63 2099.12,1800.63 2199.12,1800.63 899.12,1900.63 999.12,1900.63 1099.12,1900.63 1599.12,1900.63 1099.12,2000.63 2099.12,2000.63 2199.12,2000.63 2299.12,2000.63 2399.12,2000.63 799.12,2100.63 899.12,2100.63 999.12,2100.63 1099.12,2100.63 1599.12,2100.63 1699.12,2100.63 1799.12,2100.63 1899.12,2100.63 1999.12,2100.63 2199.12,2100.63 2399.12,2100.63
  other v2: 1630,1054.72 1584.72,1100 1675.28,1100 1630,1145.28
IDRIVE: J1.2 J1.4 J1.6 J1.8 J1.10 J1.12 U1.12 | length 1383.4
  Top Layer w10: J1.2@1380,305 J1.4@1480,305 J1.6@1580,305 J1.8@1680,305 J1.10@1780,305 J1.12@1880,305 ; v1(1475,1000) 1475,1025 1500.79,1050.79 U1.12@1555.2,1050.79
  Bottom Layer w10: J1.2@1380,305 1340,345 1340,865 v1(1475,1000)
NetC12_1: C12.1 U1.3 | length 180.2
  Top Layer w10: C12.1@1610,1342.56 1640,1312.56 U1.3@1640,1174.8
NetC12_2: C12.2 U1.4 | length 116.8
  Top Layer w10: C12.2@1610,1287.44 1610,1260 1620.16,1249.84 U1.4@1620.16,1174.8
